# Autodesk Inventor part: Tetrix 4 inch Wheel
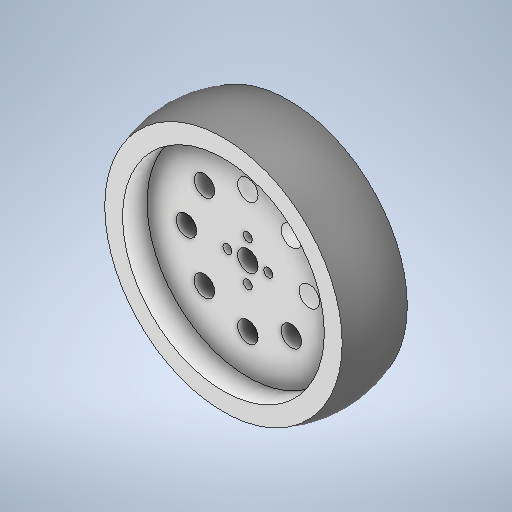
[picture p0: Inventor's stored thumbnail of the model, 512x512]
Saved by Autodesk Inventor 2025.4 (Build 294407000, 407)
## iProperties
Created: 2021-10
Part Number: Tetrix 4 inch Wheel
Material: Genérico
Document SubType Name: Modeling
Designer: usuario
Density: 1 g/cm^3
Appearance: Valor por defecto
Author: usuario
Sending System: SolidWorks 2016
Last Author: LENOVO
Last Saved: 2021-10-21
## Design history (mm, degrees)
feature "NONE"
node "Sólido1"
